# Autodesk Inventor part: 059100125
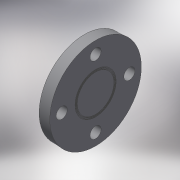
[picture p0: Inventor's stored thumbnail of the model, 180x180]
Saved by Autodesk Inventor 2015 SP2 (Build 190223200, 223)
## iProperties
Created: 2017-10
Part Number: 059100125
Material: Generic
Description: PLASSON BLANK FLANGE PVC 125
Document SubType Name: Modeling
Designer: KIM
Density: 1 g/cm^3
Appearance: Default
Author: KIM
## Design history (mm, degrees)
derived "059100.ipt"
feature "Solid1::059100.ipt"
tag "TaggingFeature1"
body "Solid1"
other parameters: "d0" = 25, "d3" = 227.7, "d12" = 45 deg, "d13" = 92, "d14" = 18, "d15" = 95.5, "d16" = 25, "d17" = 0, "d19" = 360 deg, "d21" = 1.15, "d22" = 1.15, "d23" = 1.15, "d24" = 1.15, "d25" = 1.15, "d26" = 0.46, "d27" = 0, "H_" = 25, "Dp_" = 191, "S_" = 18
